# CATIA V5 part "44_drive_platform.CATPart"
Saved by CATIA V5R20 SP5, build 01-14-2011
Part number: 44_drive_platform
Bounding box of the stored display mesh (mm): x -82.98 to 82.98, y 57.382 to 223.342, z -116.5 to -95
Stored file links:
  C:\Documents and Settings\anizard\Bureau\13\44_drive_platform.CATPart
  C:\Documents and Settings\anizard\Bureau\13\anizard.CATProduct
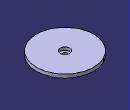
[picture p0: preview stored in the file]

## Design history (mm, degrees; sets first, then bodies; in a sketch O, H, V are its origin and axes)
External parameters (linked from other documents)
  External.diametre = 156 mm
Set1
  Plane1: linked copy from another document
  Line1: linked copy from another document
  Plane2 to Plane4: linked copy from another document
  Point1: linked copy from another document
Body1 (main body)
  Sketch1 on Plane1, origin (0, 0, 0), H (0, 1, 0), V (0, 0, 1)
    line L1 (154.1119, -95) -> (223.3619, -95)
    line L2 (223.3619, -95) -> (223.3619, -105)
    point P3 (223.3619, -105)
    arc A1 centre (220.3619, -105) radius 3 from (223.3619, -105) to (217.3619, -105) cw
    line L3 (217.3619, -105) -> (160.8619, -105)
    arc A2 centre (160.8619, -108) radius 3 from (160.8619, -105) to (157.8619, -108) ccw
    line L4 (157.8619, -108) -> (157.8619, -116.5)
    point P9 (157.8619, -116.5)
    point P10 (157.8619, -116.5)
    line L5 (157.8619, -116.5) -> (146.3619, -116.5)
    reference intersected line E1 through (0, -95) direction (-1, 0) from Plane2
    reference projected line E2 (140.3619, -199.5) -> (140.3619, -79.5) from Line1
    reference projected line E3 (140.3619, -199.5) -> (140.3619, -79.5) from Line1
    line L6 (146.3619, -116.5) -> (146.3619, -103.5)
    line L7 (146.3619, -103.5) -> (154.1119, -103.5)
    line L8 (154.1119, -103.5) -> (154.1119, -95)
    reference intersected line E4 through (0, -103.5) direction (-1, 0) from Plane3
    reference projected line E5 (140.3619, -199.5) -> (140.3619, -79.5) from Line1
    reference intersected line E6 through (0, -116.5) direction (-1, 0) from Plane4
    reference projected point E7 (146.3619, -122.5) from Point1
    distance L1 L3 = 10
    radius A1 = 3
    distance L2 E2 = 83 {= External.diametre /2 + 5mm}
    radius A2 = 3
    distance L4 E3 = 17.5
    distance E5 L8 = 13.75
    horizontal: L1 H, L3 H, L5 H, L7 H
    vertical: L2 V, L4 V, L6 V, L8 V
    tangency: A1 L2, A2 L3, L4 A2
    coincidence: P9 P10, L1 E1, P3 L3, L7 E4, L5 E6, L6 E7
  Shaft1: profile Sketch1, axis Line1, angle 360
